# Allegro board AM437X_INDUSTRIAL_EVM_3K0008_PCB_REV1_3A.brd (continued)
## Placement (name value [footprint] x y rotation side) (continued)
R404  0  [SM-7351-RES-0402]  62.99 81.91 180 bottom
R405  0  [SM-7351-RES-0402]  60.45 81.91 0 bottom
R406  0  [SM-7351-RES-0402]  57.15 81.79 180 bottom
R407  0  [SM-7351-RES-0402]  136.08 80.77 180 bottom
R408  0  [SM-7351-RES-0402]  57.15 80.77 180 bottom
R409  10K, 1%  [SM-7351-RES-0402]  111.89 80.64 180 bottom
R410  0  [SM-7351-RES-0402]  60.45 80.64 0 bottom
R411  0  [SM-7351-RES-0402]  3.3 80.14 180 bottom
R412  10K  [SM-7351-RES-0402]  24.26 79.88 90 bottom
R413  0  [SM-7351-RES-0402]  136.08 79.5 180 bottom
R414  100  [SM-7351-RES-0402]  130.3 79.5 180 bottom
R415  49.9  [SM-7351-RES-0402]  111.89 79.38 0 bottom
R416  0  [SM-7351-RES-0402]  60.45 79.38 180 bottom
R417  0  [SM-7351-RES-0402]  25.91 79.38 0 bottom
R418  2.2K  [SM-7351-RES-0402]  102.36 78.74 0 bottom
R419  0  [SM-7351-RES-0402]  100.2 78.74 0 bottom
R420  0  [SM-7351-RES-0402]  4.83 78.23 0 bottom
R421  0  [SM-7351-RES-0402]  125.86 77.85 270 bottom
R422  0  [SM-7351-RES-0603]  85.85 77.72 90 bottom
R423  0  [SM-7351-RES-0603]  84.2 77.72 90 bottom
R424  2.2K  [SM-7351-RES-0402]  102.36 77.6 0 bottom
R425  0  [SM-7351-RES-0402]  100.2 77.6 0 bottom
R426  10K  [SM-7351-RES-0402]  130.3 77.22 180 bottom
R427  0  [SM-7351-RES-0603]  96.14 76.2 90 bottom
R428  0  [SM-7351-RES-0603]  94.36 76.2 90 bottom
R429  0  [SM-7351-RES-0402]  130.94 75.69 180 bottom
R430  0  [SM-7351-RES-0402]  100.2 75.56 180 bottom
R431  0  [SM-7351-RES-0402]  18.16 74.68 0 bottom
R432  0  [SM-7351-RES-0402]  100.2 74.55 180 bottom
R433  4.7K  [SM-7351-RES-0402]  130.94 74.42 180 bottom
R434  0  [SM-7351-RES-0402]  60.32 74.04 0 bottom
R435  0  [SM-7351-RES-0402]  107.57 73.91 0 bottom
R436  0  [SM-7351-RES-0402]  107.57 72.77 0 bottom
R437  0  [SM-7351-RES-0402]  64.14 72.26 0 bottom
R438  0  [SM-7351-RES-0402]  20.95 71.25 0 bottom
R439  22  [SM-7351-RES-0402]  64.14 71.12 0 bottom
R440  0  [SM-7351-RES-0402]  107.57 70.36 180 bottom
R441  0  [SM-7351-RES-0402]  33.4 70.36 0 bottom
R442  22  [SM-7351-RES-0402]  64.14 69.85 0 bottom
R443  0  [SM-7351-RES-0402]  33.4 69.22 0 bottom
R444  0  [SM-7351-RES-0402]  89.03 68.71 270 bottom
R445  0  [SM-7351-RES-0402]  33.4 68.07 0 bottom
R446  0  [SM-7351-RES-0603]  25.4 67.28 270 bottom
R447  0  [SM-7351-RES-0402]  33.4 66.93 0 bottom
R448  0  [SM-7351-RES-0603]  2.79 66.9 270 bottom
R449  0  [SM-7351-RES-0402]  64.14 66.67 0 bottom
R450  0  [SM-7351-RES-0402]  101.98 66.04 180 bottom
R451  0  [SM-7351-RES-0603]  119.31 65.66 270 bottom
R452  2.2K  [SM-7351-RES-0402]  33.4 65.63 180 bottom
R453  0  [SM-7351-RES-0402]  64.14 65.53 0 bottom
R454  0  [SM-7351-RES-0402]  101.98 64.9 180 bottom
R455  2.2K  [SM-7351-RES-0402]  33.4 64.48 0 bottom
R456  0  [SM-7351-RES-0603]  70.48 64.39 180 bottom
R457  0  [SM-7351-RES-0402]  64.14 64.39 0 bottom
R458  10K  [SM-7351-RES-0402]  59.94 63.88 270 bottom
R459  0  [SM-7351-RES-0402]  33.4 63.25 180 bottom
R460  12K, 1%  [SM-7351-RES-0402]  122.55 62.74 90 bottom
R461  0  [SM-7351-RES-0402]  33.4 62.23 0 bottom
R462  2.2K  [SM-7351-RES-0402]  27.43 62.23 0 bottom
R463  0  [SM-7351-RES-0603]  70.48 61.85 180 bottom
R464  4.87K  [SM-7351-RES-0402]  25.15 61.59 90 bottom
R465  0  [SM-7351-RES-0402]  65.41 61.09 0 bottom
R466  0  [SM-7351-RES-0402]  33.4 61.09 0 bottom
R467  0  [SM-7351-RES-0402]  90.9 60.29 0 bottom
R468  0  [SM-7351-RES-0402]  61.09 59.31 0 bottom
R469  0  [SM-7351-RES-0402]  64.14 59.18 0 bottom
R470  2.2K, 1/8W  [SM-7351-RES-0402]  80.9 58.93 0 bottom
R471  0  [SM-7351-RES-0402]  64.14 57.91 0 bottom
R472  10K  [SM-7351-RES-0402]  134.11 56.77 90 bottom
R473  0  [SM-7351-RES-0402]  64.14 56.64 0 bottom
R474  2.2K, 1/8W  [SM-7351-RES-0402]  81.66 56.39 270 bottom
R475  0  [SM-7351-RES-0402]  3.94 56.35 180 bottom
R476  4.99K  [SM-7351-RES-0402]  104.14 56.26 180 bottom
R477  0  [SM-7351-RES-0402]  134.11 54.1 270 bottom
R478  0  [SM-7351-RES-0402]  133.1 54.1 90 bottom
R479  10K  [SM-7351-RES-0402]  108.08 53.09 270 bottom
R480  49.9  [SM-7351-RES-0402]  45.97 51.82 180 bottom
R481  18K  [SM-7351-RES-0402]  45.97 50.55 0 bottom
R482  0  [SM-7351-RES-0402]  114.81 49.91 0 bottom
R483  0  [SM-7351-RES-0603]  5.71 47.62 270 bottom
R484  0  [SM-7351-RES-0402]  74.17 47.5 90 bottom
R485  0  [SM-7351-RES-0603]  9.02 47.37 270 bottom
R486  0  [SM-7351-RES-0603]  45.02 46.99 180 bottom
R487  0  [SM-7351-RES-0402]  133.86 46.86 270 bottom
R488  0  [SM-7351-RES-0603]  110.56 46.86 0 bottom
R489  0  [SM-7351-RES-0402]  127.64 45.59 90 bottom
R490  0  [SM-7351-RES-0402]  41.27 43.43 270 bottom
R491  15K,1%  [SM-7351-RES-0402]  109.6 43.31 180 bottom
R492  49.9  [SM-7351-RES-0402]  109.6 42.04 0 bottom
R493  0  [SM-7351-RES-0603]  20.95 41.78 90 bottom
R494  0  [SM-7351-RES-0402]  63.12 40.51 180 bottom
R495  4.99K  [SM-7351-RES-0402]  38.61 39.5 90 bottom
R496  4.99K  [SM-7351-RES-0402]  41.91 38.86 270 bottom
R497  22K  [SM-7351-RES-0402]  61.98 37.97 270 bottom
R498  100  [SM-7351-RES-0402]  131.44 37.72 180 bottom
R499  100  [SM-7351-RES-0402]  131.44 36.58 0 bottom
R500  33  [SM-7351-RES-0402]  55.63 36.2 180 bottom
R501  22K  [SM-7351-RES-0402]  61.98 35.94 90 bottom
R502  19.1K  [SM-7351-RES-0402]  59.94 35.94 270 bottom
R503  47  [SM-7351-RES-0402]  98.68 35.81 180 bottom
R504  240  [SM-7351-RES-0402]  79.63 35.56 0 bottom
R505  33  [SM-7351-RES-0402]  49.4 35.56 90 bottom
R506  19.1K  [SM-7351-RES-0402]  28.58 34.42 270 bottom
R507  49.9  [SM-7351-RES-0402]  100.33 34.16 180 bottom
R508  49.9  [SM-7351-RES-0402]  100.33 33.15 180 bottom
R509  22K  [SM-7351-RES-0402]  62.99 32.77 90 bottom
R510  19.1K  [SM-7351-RES-0402]  49.4 32.26 90 bottom
R511  49.9K  [SM-7351-RES-0402]  52.45 31.75 270 bottom
R512  120  [SM-7351-RES-0402]  7.62 31.12 0 bottom
R513  0  [SM-7351-RES-0603]  19.94 30.1 0 bottom
R514  0  [SM-7351-RES-0603]  15.24 30.1 0 bottom
R515  0  [SM-7351-RES-0402]  32.26 29.97 90 bottom
R516  47  [SM-7351-RES-0402]  100.46 29.08 180 bottom
R517  47  [SM-7351-RES-0402]  85.09 28.83 0 bottom
R518  22K  [SM-7351-RES-0402]  50.29 28.83 270 bottom
R519  10K  [SM-7351-RES-0402]  14.61 28.19 0 bottom
R520  47  [SM-7351-RES-0402]  100.46 27.94 180 bottom
R521  47  [SM-7351-RES-0402]  85.09 27.81 0 bottom
R522  47  [SM-7351-RES-0402]  85.09 26.8 0 bottom
R523  22K  [SM-7351-RES-0402]  63.5 26.54 90 bottom
R524  22K  [SM-7351-RES-0402]  62.48 26.54 90 bottom
R525  19.1K  [SM-7351-RES-0402]  60.45 26.54 270 bottom
R526  0  [SM-7351-RES-0603]  15.24 26.29 0 bottom
R527  47  [SM-7351-RES-0402]  95.76 25.27 90 bottom
R528  47  [SM-7351-RES-0402]  94.61 25.27 90 bottom
R529  47  [SM-7351-RES-0402]  93.47 25.27 90 bottom
R530  47  [SM-7351-RES-0402]  92.33 25.27 90 bottom
R531  47  [SM-7351-RES-0402]  91.19 25.27 90 bottom
R532  47  [SM-7351-RES-0402]  90.04 25.27 90 bottom
R533  47  [SM-7351-RES-0402]  88.9 25.27 90 bottom
R534  47  [SM-7351-RES-0402]  87.76 25.27 90 bottom
R535  47  [SM-7351-RES-0402]  86.61 25.27 90 bottom
R536  0.02  [SM-7351-RES-1206]  46.1 24.77 270 bottom
R537  0.02  [SM-7351-RES-1206]  43.18 24.77 270 bottom
R538  0.02  [SM-7351-RES-1206]  40.26 24.77 270 bottom
R539  22K  [SM-7351-RES-0402]  64.52 24.51 90 bottom
R540  0  [SM-7351-RES-0603]  15.24 24.38 0 bottom
R541  0  [SM-7351-RES-0402]  28.96 21.21 180 bottom
R542  10K  [SM-7351-RES-0402]  28.96 20.07 180 bottom
R543  0  [SM-7351-RES-1210]  42.67 19.56 90 bottom
R544  4.7K  [SM-7351-RES-0402]  37.72 17.65 270 bottom
R545  4.7K  [SM-7351-RES-0402]  36.7 17.65 270 bottom
R546  4.7K  [SM-7351-RES-0402]  35.69 17.65 270 bottom
R547  4.7K  [SM-7351-RES-0402]  34.67 17.65 270 bottom
R548  470K  [SM-7351-RES-0402]  53.09 16.89 180 bottom
R549  10K  [SM-7351-RES-0402]  97.28 15.62 180 bottom
R550  10K  [SM-7351-RES-0402]  58.29 13.84 0 bottom
R551  10K  [SM-7351-RES-0402]  58.26 12.83 0 bottom
R552  4.99K  [SM-7351-RES-0402]  17.65 12.32 270 bottom
R553  4.99K  [SM-7351-RES-0402]  37.59 12.1 270 bottom
R554  4.99K  [SM-7351-RES-0402]  25.6 11.91 270 bottom
R555  4.99K  [SM-7351-RES-0402]  29.77 11.82 270 bottom
R556  10K  [SM-7351-RES-0402]  58.26 11.68 0 bottom
R557  10K  [SM-7351-RES-0402]  58.26 10.54 0 bottom
R558  0  [SM-7351-RES-0402]  38.73 9.94 270 bottom
R559  95.3K  [SM-7351-RES-0402]  37.59 9.94 270 bottom
R560  4.99K  [SM-7351-RES-0402]  17.65 9.78 270 bottom
R561  0  [SM-7351-RES-0402]  25.6 9.75 270 bottom
R562  95.3K  [SM-7351-RES-0402]  24.46 9.75 270 bottom
R563  0  [SM-7351-RES-0402]  30.91 9.66 270 bottom
R564  95.3K  [SM-7351-RES-0402]  29.77 9.66 270 bottom
R565  4.99K  [SM-7351-RES-0402]  17.65 7.24 270 bottom
R566  0  [SM-7351-RES-0402]  70.23 83.31 270 top
SCKT1  AM437X ZDN Socket  [SCKBGA625]  80.48 66.9 90 top
SW1  B3SL  [SW_B3SL-1022P]  134.11 57.4 0 top
SW2  B3SL  [SW_B3SL-1022P]  134.05 35.69 0 top
TP1  TP  [TH_TP_5002]  57.53 117.35 0 top
TP2  TP  [TH_TP_5002]  55.12 101.09 0 top
TP3  TP1mm  [TP_SMD1MMCIRCLE]  25.27 96.36 0 top
TP4  TP1mm  [TP_SMD1MMCIRCLE]  135.76 92.33 0 top
TP5  TP1mm  [TP_SMD1MMCIRCLE]  135.76 90.3 0 top
TP6  TP1mm  [TP_SMD1MMCIRCLE]  125.6 83.95 0 top
TP7  TP  [TH_TP_5002]  95.5 83.57 0 top
TP8  TP1mm  [TP_SMD1MMCIRCLE]  25.27 72.01 0 top
TP9  TP  [TH_TP_5002]  137.41 71.88 0 top
TP10  TP1mm  [TP_SMD1MMCIRCLE]  110.24 70.74 0 top
TP11  TP  [TH_TP_5002]  2.67 52.7 0 top
TP12  TP  [TH_TP_5002]  31.88 46.61 0 top
TP13  TP  [TH_TP_5002]  103 40.51 0 top
TP14  TP  [TH_TP_5002]  123.19 34.29 0 top
TP15  TP  [TH_TP_5002]  21.34 26.29 0 top
TP16  TP  [TH_TP_5002]  63.88 2.92 0 top
TP17  TP1mm  [TP_SMD1MMCIRCLE]  116.84 107.7 90 bottom
TP18  TP1mm  [TP_SMD1MMCIRCLE]  35.94 85.09 180 bottom
TP19  TP1mm  [TP_SMD1MMCIRCLE]  75.56 79.38 180 bottom
TP20  TP1mm  [TP_SMD1MMCIRCLE]  80.77 77.72 180 bottom
TP21  TP1mm  [TP_SMD1MMCIRCLE]  65.66 77.22 180 bottom
U1  Red_Green_Yellow_LED  [LED-SM1210]  12.07 116.46 0 top
U2  Red_Green_Yellow_LED  [LED-SM1210]  20.07 116.46 0 top
U3  TPS5402D  [SOIC-8]  56.7 108.46 270 top
U4  SN65HVS882  [U_28_PWP]  75.56 101.66 0 top
U5  TPIC2810  [U_16_D]  87.76 101.46 180 top
U6  SN74LVC8T245  [TSSOP8X4-24-47M]  112.87 95.22 270 top
U7  TLK105L  [QFN5X5-32-39M]  27.56 91.28 270 top
U8  SN74LVC1G04  [SC70-5-43M]  120.65 83.82 180 top
U9  SN74LV244A  [TSSOP4X6-20]  60.07 82.3 90 top
U10  TPS5402D  [SOIC-8]  117.41 78.74 90 top
U11  -  [AM437X_ZDN]  80.48 67.15 90 top
U12  TLK105L  [QFN5X5-32-39M]  27.56 66.01 270 top
U13  FT2232HL  [LQFP64PIN]  117.23 60.96 180 top
U14  TPS5402D  [SOIC-8]  21.46 55.31 180 top
U15  TPS5402D  [SOIC-8]  40.45 52.45 270 top
U16  93LC56B  [SOIC_8]  114.17 47.5 90 top
U17  TPS5402D  [SOIC-8]  115.13 41.4 90 top
U18  OPA365  [SOT23-5]  28.58 35.56 90 top
U19  OPA365  [SOT23-5]  61.09 35.18 90 top
U20  MT41K256M16HA  [BGA9X14-96]  73.66 34.42 0 top
U21  MT41K256M16HA  [BGA9X14-96]  92.33 34.42 0 top
U22  OPA365  [SOT23-5]  50.29 32.38 270 top
U23  DRV8313  [HTSSOP-28P-47M]  42.42 31.75 0 top
U24  OPA365  [SOT23-5]  61.09 25.91 90 top
U25  TPS51200  [DRCPSO_10PIN]  93.85 14.22 180 top
U26  TPS386000  [QFN4X4-20-39M]  63.34 12.45 270 top
U27  TPD6E001  [U_10_RSE]  47.37 4.83 270 top
U28  LM4132  [SOT23-5]  127.25 114.55 270 bottom
U29  TPS22922B  [WCSP1X1-6-20M]  66.17 107.95 90 bottom
U30  TPS79301  [U_6_DBV]  109.86 104.58 90 bottom
U31  TXS0102  [DCT8]  134.05 102.68 90 bottom
U32  CAT24C256W  [SOIC_8]  85.22 101.46 180 bottom
U33  CDCE913  [TSSOP5X4-14-47M]  23.88 100.33 180 bottom
U34  SN74AVC1T45  [SMDSC70-6]  125.98 94.23 180 bottom
U35  TPS62362  [BGA2X2-16]  101.95 93.18 0 bottom
U36  SN74LVC1G07  [U_5_DCK]  74.3 92.96 90 bottom
U37  KSZ9031RN  [QFN7X7-48]  43.18 92.71 270 bottom
U38  SN74AVC4T245  [U_16_PW]  133.35 92.46 180 bottom
U39  SN74LV244A  [TSSOP4X6-20]  60.07 89.79 90 bottom
U40  TPS22922B  [WCSP1X1-6-20M]  115.7 84.2 0 bottom
U41  SN74AVC2T244  [SON2X1-8-16M]  130.81 83.95 180 bottom
U42  SN74LVC1G07  [U_5_DCK]  30.35 81.03 180 bottom
U43  SN74LVC1G08  [SM-SO-SC70-5]  22.23 80.36 180 bottom
U44  SN74LVC1G08  [SM-SO-SC70-5]  15.49 75.69 180 bottom
U45  SN74AVC4T245  [U_16_PW]  126.75 69.6 180 bottom
U46  MX66L51235FMI  [SOIC_16PIN_DW]  42.55 65.28 90 bottom
U47  TPD2E001  [U_5_DRL]  131.95 62.86 180 bottom
U48  SN74LVC1G07  [U_5_DCK]  107.44 56.26 180 bottom
U49  SN74AVC2T244  [SON2X1-8-16M]  132.21 50.16 180 bottom
U50  SN74LVC1G00DCK  [U_5_DCK]  123.82 48.9 180 bottom
U51  SN74LVC1G07  [SC70-5-43M]  127 48.77 270 bottom
U52  TPS22922B  [WCSP1X1-6-20M]  42.16 46.99 180 bottom
U53  TPS22922B  [WCSP1X1-6-20M]  113.41 46.86 0 bottom
U54  SN74LVC1G07  [SC70-5-43M]  134.49 43.56 270 bottom
U55  SN65HVD78D  [SOIC_8]  24.64 43.43 180 bottom
U56  REF3025  [SOT23-3-44M]  53.85 38.99 180 bottom
U57  SN65HVD78D  [SOIC_8]  7.49 27.56 270 bottom
U58  SN74LVC8T245  [TSSOP8X4-24-47M]  34.42 24.64 270 bottom
U59  TPD2E001  [U_5_DRL]  53.21 18.67 90 bottom
Y1  24MHz  [XTAL2X3-30M]  72.99 88.87 90 top
Y2  25MHz  [SM_OSC_ABM3]  21.08 107.7 0 bottom
Y3  32.768KHz MC-306  [MC-306]  98.26 61.05 0 bottom
Y4  12MHz  [SM_OSC_ABM3]  126.43 56.01 90 bottom

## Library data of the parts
C1 C51 C67 C88 C96 C97 C99 C121 C122 C253 C326 C327 C337 = 1C_0.1uFCapacitor50V10%0402: Tolerance: TOLERANCE; User Part Number: USERPART#
C2 C21 C22 C28 C31 C43 C104 C105 C113 C117 C123 C134 C136 C161 C167 C168 C172 C182 C189 C214 C229 C244 C257 C266 C276 C280 C335 C341 C342 = 1C_10uFCapacitor16V10%0805
C3-C10 = 1C_0.022uFCapacitor16Vsmd0402: Tolerance: TOLERANCE; User Part Number: USERPART#
C11 C46 C72 C75 C82 = 1C_2200pFCapacitor50V10%SMD0402: Tolerance: TOLERANCE; User Part Number: USERPART#
C12 C45 C70 C74 C81 C95 C339 = 1C_10uFCapacitor35V10%0805
C13-C18 C20 C24 C25 C29 C30 C32-C34 C37 C39-C41 C44 C47 C48 C52 C53 C58-C64 C66 C69 C73 C76 C77 C79 C89 C90 C92 C94 C101 C114 C119 C126 C127 C139-C141 C145 C146 C152 C156 C158-C160 C166 C169 C170 C173 C178-C181 C183-C185 C187 C190 C192 C193 C195-C207 C209-C211 C213 C216 C217 C219-C221 C223-C227 C230 C231 C233-C236 C238-C242 C246 C247 C249 C250 C252 C256 C259 C260 C263-C265 C267 C270 C274 C275 C277-C279 C281-C285 C288-C292 C294-C297 C299 C301 C302 C304 C314-C316 C318-C320 C323 C324 C328 C329 C336 C343-C346 = 1C_0.01uFCapacitor16V10%0402: Tolerance: TOLERANCE; User Part Number: USERPART#
C19 C71 C151 C186 C191 C212 C218 C287 = 1C_1uFCapacitor10V10%0402: Tolerance: TOLERANCE; User Part Number: USERPART#
C23 C303 = 1C_10uFCapacitor50V10%1206
C26 C38 C55 C57 C65 C78 C103 C106 C107 C112 C116 C125 C142 C143 C147-C150 C153 C155 C157 C162-C164 C174 C194 C208 C215 C222 C232 C237 C306 C307 C311-C313 C317 C330 C338 = 1C_0.1uFCapacitor16V10%0402: Tolerance: TOLERANCE; User Part Number: USERPART#
C27 C131 C271 = 1C_220uFCapacitor16V10%Tantalum
C35 C36 = 1C_24pFCapacitor50V5%SMD0402: Tolerance: TOLERANCE; User Part Number: USERPART#
C49 C50 = 1C_47uFCapacitor16V20%1206
C54 C56 C109-C111 C154 C300 C308 C321 C332 C347 C351 C352 = 1C_0.001uFCapacitor50V5%0402: Tolerance: TOLERANCE; User Part Number: USERPART#
C68 C348-C350 = 1C_47nFCapacitor25V10%smd0402: Tolerance: TOLERANCE; User Part Number: USERPART#
C80 C102 C124 C175 C254 C269 C272 = 1C_22uFCapacitor16V10%0805
C83 C84 C286 C309 C325 C333 C334 = 1C_180pF50V5%SMD0402: Tolerance: TOLERANCE; User Part Number: USERPART#
C85 C86 C91 C93 C176 C177 C298 C305 C310 C331 = 1C_100pFCapacitor16V10%0402: Tolerance: TOLERANCE; User Part Number: USERPART#
C87 C100 C293 = 1C_0.47uFCapacitor16V10%0402: Tolerance: TOLERANCE; User Part Number: USERPART#
C98 = 1C_1uFCapacitor50V10%0603: Tolerance: TOLERANCE; User Part Number: USERPART#
C108 = 1C_10pFCapacitor50V1%smd0402: Tolerance: TOLERANCE; User Part Number: USERPART#
C115 C120 C245 C251 C258 = 1C_4.7uFCapacitor16V10%0603
C118 C171 C262 C268 C273 = 1C_1uFCapacitor50V10%0603
C128 C138 C228 = 1C_2.2uF16V10%SMD0805
C129 C130 C255 C261 = 1C_18pFCapacitor16V10%0402: Tolerance: TOLERANCE; User Part Number: USERPART#
C132 C133 = 1C_2.2uFCapacitor6.3V10%smd0603
C135 C243 C248 = 1C_15pFCapacitor50V10%smd0402: Tolerance: TOLERANCE; User Part Number: USERPART#
C137 C188 = 1C_4700pFCapacitor50V10%0402: Tolerance: TOLERANCE; User Part Number: USERPART#
C144 C165 = 1C_10uFCapacitor6.3V20%0603
C322 C340 = 1C_100uFCapacitor35V20%ElecPoly
D1 D11 D13 D14 D16 = 1E_Diode_500mA30V
D2-D10 D12 = 1F_LED_Green
D15 = 1F_LED_Red
D17 D19 D22 = 1E_Diode_MBRS140T3
D18 D21 = 1E_Diode_SMCJ26CA
D20 = Diode200mA250V
F1 = 1P_Fuse_4A
FB1 FB6-FB12 FB14 FB17 = 1L_FerBead_180ohm200mA
FB2-FB5 = 1L_FerriteBead_600mA10ohm
FB13 FB15 FB16 = 1L_FerriteBead_220ohm2A
J1 = Header20x2_0.1in_Female
J2 = 2H_Header_3x1
J3 = 2H_Header5x2
J4 = 2J_ConnectorRJ45_Gigabit
J5 = 2C_Conn_FPC_AXK_24pin
J6 J9 = 2J_ConnectorRJ45_10_100MbAMDIX
J7 = 2H_Header10x2_CJTAG
J8 J11 = 2H_Header_2x1
J10 = 2C_Conn_M12_8pin_female
J12 = 2J_Conn_PwrJack_RAPC722
J13 J14 = 2C_Conn_LeadScrewDown_2pin
J15 = 2H_Header_6x1
J16 = 2H_Header30x2_female_2mm
J17 = 2C_Conn_LeadScrewDown_3pin
J18 = 2C_MicroUSBAB
J19 = 2C_Conn_microSD_8: User Part Number: X; Tolerance: X
L1-L3 = 1L_4.7uHInductor30%3.1Asmd
L4 = 1L_47uHInductor20%1.6Asmd
L5 = 1L_1uHInductor20%4.5Asmd
L6 = 1L_100uHInductor20%450mAsmd
L7 = 1L_100uHInductor20%1.02Asmd
L8 = 1L_82uHInductor20%370mAsmd
L9 = 1L_47uHInductor20%720mAsmd
Q1-Q8 = 1Q_MOSFET_NChan_BSS138
Q9 = 1Q_MOSFET_PChan_FDT434P
Q10 = 1Q_MOSFET_PChan_BSS84
R1 R7 R9 R11 R23-R30 R35-R42 R47-R49 R233 R274 R276 R278 R361 = 1R_100KOhmResistor1/16W0402
R2 R3 R54 R69 R75 R81 R135 R169 R172 R178 R224 R226 R228 R231 R234 R236 R237 R244 R266 R267 R297 R300 R305 R314-R321 R328-R336 R340-R343 R345 R347 R392 R393 R395 R396 R399 R400 R412 R426 R458 R472 R479 R519 R542 R549-R551 R556 R557 = 1R_10KOhmResistor1/16W0402
R4-R6 R268 R271 R272 R280-R287 = 1R_150ohm1/16W1%SMD0402
R8 R10 R12 R21 R22 R52 R60-R63 R65 R70-R74 R80 R83-R92 R97-R99 R103-R105 R109-R120 R124 R126 R129 R132-R134 R138 R140 R143 R148 R152 R157 R163 R170 R186 R187 R202 R232 R238-R243 R245-R265 R275 R277 R279 R296 R304 R308-R310 R324 R325 R348 R350-R352 R354-R357 R359 R360 R363 R364 R374-R376 R380-R385 R388 R404 R406-R408 R411 R413 R416 R417 R419-R421 R425 R429-R432 R434-R438 R440 R444 R450 R454 R459 R465 R467 R468 R471 R473 R475 R477 R478 R482 R487 R489 R490 R494 R515 R541 R558 R561 R563 R566 = 1R_ZeroOhmResistor1/16W0402
R13 R17 R139 R142 R149 R190 R215 R273 R299 R303 R313 R346 R358 R379 R401 R422 R423 R427 R428 R446 R448 R451 R456 R463 R483 R485 R486 R488 R493 R513 R514 R526 R540 = 1R_ZeroOhmResistor1/16W0603
R14 = 1R_34KOhmResistor1/10W1%0402
R15 R16 R160 R168 R353 R402 R403 R433 R544-R547 = 1R_4.7KOhmResistor1/16W0402
R18 R94 R156 R175 R182 = 1R_51Kohm1/16W1%smd0402
R19 = 1R_4.75KohmResistor1/16W1%0402
R20 R201 R204 R223 R311 R312 R323 R386 R387 R500 R505 = 1R_33ohmResistor1/16W5%0402
R31 R43 R50 R56 R101 R106 R125 R131 R162 R164 R302 R415 R480 R492 R507 R508 = 1R_49.9OhmResistor1/16W0402
R32 = 1R_12.1KohmResistor1/16W1%0402
R33 R34 = ZeroOhmResistor1/16W0402
R44 R46 R51 R55 R57 R77 R96 R100 R108 R122 R145 R180 R418 R424 R452 R462 = 1R_2.2KOhmResistor1/16W0402
R45 R53 R193 R195 R197 R200 R203 R209 R211 R222 R366 R369 R372 R394 R397 R398 = 1R_1KOhmResistor1/16W0402
R58 R64 R68 = 1R_4.02KohmResistor1/16W1%0402
R59 R67 R76 R78 R79 R128 R136 R137 R141 R144 R146 R147 R150 R151 R153 R155 R158 R161 R167 R174 R177 R179 R337 R339 R344 R349 R377 R378 R390 R391 R405 R410 R441 R443 R445 R447 R449 R453 R457 R461 R466 R469 R484 = 1R_ZeroOhmResistor1/16W0402: signal model: 1R_ZEROOHMRESISTOR1/16W0402_SM-_0
R66 = 1R_1.5KohmResistor1/16W5%0402
R82 R307 = 1MOhmResistor1/16W0402
R93 = 1R_8.06Kohm1/16W1%smd0402
R95 R235 = 1R_60.4Kohm1/16W1%smd0402
R102 R107 R121 R123 R365 R367 R368 R370 R371 R373 R439 R442 = 1R_22OhmResistor1/16W1%0402: signal model: 1R_22OHMRESISTOR1/16W1%0402_SM-_22
R127 R130 R455 = 1R_2.2KOhmResistor1/16W0402: signal model: 1R_2.2KOHMRESISTOR1/16W0402_SM-_2.2K
R154 R559 R562 R564 = 95.3KOhmResistor1/16W0402
R159 R173 R191 R192 R212 R511 = 1R_49.9KOhmResistor1/16W0402
R165 = 1R_16KOhmResistor1/16W1%0402
R166 = 1R_3.01KohmResistor1/16W1%0402
R171 R183 R269 R270 = 1R_220ohm1/10W1%smd0402
R176 = 1R_20.5Kohm1/16W1%smd0402
R181 = 1R_40.2Kohm1/16W1%smd0402
R184 R185 R188 R189 R207 R497 R501 R509 R518 R523 R524 R539 = 1R_22Kohm1/16W1%SMD0402
R194 R196 R208 R210 = 1R_28.7Kohm1/16W1%smd0402
R198 R504 = 1R_240OhmResistor1/16W0402
R199 R205 R206 R216-R221 R503 R516 R517 R520-R522 R527-R535 = 1R_47ohm1/16W1%smd0402
R213 R476 R495 R496 R552-R555 R560 R565 = 1R_4.99KOhmResistor1/16W0402
R214 = 1R_402Kohm1/16W1%smd0402
R225 = 1R_10ohm1/16W5%smd0402
R227 R230 = 1R_14KOhmResistor1/16W0402
R229 = 1R_24Kohm1/16W1%smd0402
R288-R295 = 1R_1.2Kohm1/3W1%SMDMELF0102
R298 R491 = 1R_15Kohm1/16W1%smd0402
R301 = 1R_30.1Kohm1/16W1%smd0402
R306 = 1R_39Kohm1/16W5%smd0402
R322 = 1R_25Kohm1/10W0.1%smd0603
R326 R327 = 1R_ZeroOhmResistor1/16W0603: signal model: 1R_ZEROOHMRESISTOR1/16W0603_SM-_0
R338 = 49.9ohm1/3W1%SMDMELF0102
R362 R464 = 1R_4.87Kohm1/16W1%smd0402
R389 R414 R498 R499 = 1R_100ohm1/16W1%SMD0402
R409 = 1R_10KOhmResistor1/10W1%0402
R460 = 1R_12Kohm1/16W1%SMD0402
R470 R474 = 1R_2.2KohmResistor1/8W1%0402
R481 = 1R_18KohmResistor1/10W1%smd0402
R502 R506 R510 R525 = 1R_19.1Kohm1/16W1%smd0402
R512 = 1R_120ohm1/16W1%smd0402
R536-R538 = 1R_0.02ohm1W1%smd1206
R543 = 1R_ZeroOhmResistor1/2W1210
R548 = 470Kohm1/16W1%SMD0402
SCKT1 = AM437X_ZDN_Processor_Socket
SW1 SW2 = 2W_Switch_Pushbuttonsmd
TP1 TP2 TP7 TP9 TP11-TP16 = 2H_TestPointThroughHole
TP3-TP6 TP8 TP10 TP17-TP21 = 2H_Testpoint_SMD1mmCircle
U1 U2 = 1F_LED_Tricolor_RedGreenYellow
U3 U10 U14 U15 U17 = 1A_TPS5402
U4 = SN65HVS882
U5 = TPIC2810
U6 U58 = 1A_SN74LVC8T245
U7 U12 = 1A_TLK105L
U8 = 1A_SN74LVC1G04
U9 U39 = 1A_SN74LV244APWRG3
U11 = am437x_ZDN_Industrial EVM
U13 = 1A_FT2232_2
U16 = 1A_93C56EEPROM2Kbit
U18 U19 U22 U24 = 1A_OPA365
U20 U21 = 1A_MT41K256M16HA
U23 = 1A_DRV8313
U25 = TPS51200
U26 = 1A_TPS386000
U27 = 1A_TPD6E001RSE
U28 = 1A_LM4132
U29 U40 U52 U53 = 1A_TPS22922B
U30 = 1A_TPS79301
U31 = 1A_TXS0102
U32 = 1A_CAT24C256W
U33 = 1A_CDCE913
U34 = 1A_SN74AVC1T45
U35 = 1A_TPS62362
U36 U42 U48 U51 U54 = 1A_SN74LVC1G07
U37 = 1A_KSZ9031RNX
U38 U45 = 1A_SN74AVC4T245
U41 U49 = 1A_SN74AVC2T244
U43 U44 = SN74LVC1G08DCKT_SC70
U46 = 1A_MX66L51235FMI
U47 U59 = 1A_TPD2E001DRL
U50 = 1A_SN74LVC1G00DCK
U55 U57 = 1A_SN65HVD78
U56 = 1A_REF3025
Y1 = 1Y_Crystal24MHzSCM
Y2 = 1Y_Crystal25MHzABM3
Y3 = 1Y_Crystal_SMD32_768kHz
Y4 = 1Y_Crystal12MHzABM3

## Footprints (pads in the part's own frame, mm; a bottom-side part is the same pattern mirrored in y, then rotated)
AM437X_ZDN
  round 0.28 smd: A1(-7.8,7.8) A2(-7.15,7.8) A3(-6.5,7.8) A4(-5.85,7.8) A5(-5.2,7.8) A6(-4.55,7.8) A7(-3.9,7.8) A8(-3.25,7.8) A9(-2.6,7.8) A10(-1.95,7.8) A11(-1.3,7.8) A12(-0.65,7.8) A13(0,7.8) A14(0.65,7.8) A15(1.3,7.8) A16(1.95,7.8) A17(2.6,7.8) A18(3.25,7.8) A19(3.9,7.8) A20(4.55,7.8) A21(5.2,7.8) A22(5.85,7.8) A23(6.5,7.8) A24(7.15,7.8) A25(7.8,7.8) AA1(-7.8,-5.2) AA2(-7.15,-5.2) AA3(-6.5,-5.2) AA7(-3.9,-5.2) AA9(-2.6,-5.2) AA10(-1.95,-5.2) AA12(-0.65,-5.2) AA13(0,-5.2) AA15(1.3,-5.2) AA16(1.95,-5.2) AA18(3.25,-5.2) AA19(3.9,-5.2) AA23(6.5,-5.2) AA24(7.15,-5.2) AA25(7.8,-5.2) AB1(-7.8,-5.85) AB2(-7.15,-5.85) AB6(-4.55,-5.85) AB7(-3.9,-5.85) AB9(-2.6,-5.85) AB10(-1.95,-5.85) AB12(-0.65,-5.85) AB13(0,-5.85) AB15(1.3,-5.85) AB16(1.95,-5.85) AB18(3.25,-5.85) AB19(3.9,-5.85) AB20(4.55,-5.85) AB24(7.15,-5.85) AB25(7.8,-5.85) AC1(-7.8,-6.5) AC2(-7.15,-6.5) AC3(-6.5,-6.5) AC5(-5.2,-6.5) AC6(-4.55,-6.5) AC7(-3.9,-6.5) AC9(-2.6,-6.5) AC10(-1.95,-6.5) AC12(-0.65,-6.5) AC13(0,-6.5) AC15(1.3,-6.5) AC16(1.95,-6.5) AC18(3.25,-6.5) AC20(4.55,-6.5) AC21(5.2,-6.5) AC23(6.5,-6.5) AC24(7.15,-6.5) AC25(7.8,-6.5) AD1(-7.8,-7.15) AD2(-7.15,-7.15) AD3(-6.5,-7.15) AD4(-5.85,-7.15) AD5(-5.2,-7.15) AD6(-4.55,-7.15) AD7(-3.9,-7.15) AD8(-3.25,-7.15) AD9(-2.6,-7.15) AD10(-1.95,-7.15) AD11(-1.3,-7.15) AD12(-0.65,-7.15) AD13(0,-7.15) AD14(0.65,-7.15) AD15(1.3,-7.15) AD16(1.95,-7.15) AD17(2.6,-7.15) AD18(3.25,-7.15) AD19(3.9,-7.15) AD20(4.55,-7.15) AD21(5.2,-7.15) AD22(5.85,-7.15) AD23(6.5,-7.15) AD24(7.15,-7.15) AD25(7.8,-7.15) AE1(-7.8,-7.8) AE2(-7.15,-7.8) AE3(-6.5,-7.8) AE4(-5.85,-7.8) AE5(-5.2,-7.8) AE6(-4.55,-7.8) AE7(-3.9,-7.8) AE8(-3.25,-7.8) AE9(-2.6,-7.8) AE10(-1.95,-7.8) AE11(-1.3,-7.8) AE12(-0.65,-7.8) AE13(0,-7.8) AE14(0.65,-7.8) AE15(1.3,-7.8) AE16(1.95,-7.8) AE17(2.6,-7.8) AE18(3.25,-7.8) AE19(3.9,-7.8) AE20(4.55,-7.8) AE21(5.2,-7.8) AE22(5.85,-7.8) AE23(6.5,-7.8) AE24(7.15,-7.8) AE25(7.8,-7.8) B1(-7.8,7.15) B2(-7.15,7.15) B3(-6.5,7.15) B4(-5.85,7.15) B5(-5.2,7.15) B6(-4.55,7.15) B7(-3.9,7.15) B8(-3.25,7.15) B9(-2.6,7.15) B10(-1.95,7.15) B11(-1.3,7.15) B12(-0.65,7.15) B13(0,7.15) B14(0.65,7.15) B15(1.3,7.15) B16(1.95,7.15) B17(2.6,7.15) B18(3.25,7.15) B19(3.9,7.15) B20(4.55,7.15) B21(5.2,7.15) B22(5.85,7.15) B23(6.5,7.15) B24(7.15,7.15) B25(7.8,7.15) C1(-7.8,6.5) C2(-7.15,6.5) C3(-6.5,6.5) C5(-5.2,6.5) C6(-4.55,6.5) C8(-3.25,6.5) C10(-1.95,6.5) C11(-1.3,6.5) C13(0,6.5) C14(0.65,6.5) C16(1.95,6.5) C17(2.6,6.5) C19(3.9,6.5) C20(4.55,6.5) C21(5.2,6.5) C23(6.5,6.5) C24(7.15,6.5) C25(7.8,6.5) D1(-7.8,5.85) D2(-7.15,5.85) D6(-4.55,5.85) D7(-3.9,5.85) D8(-3.25,5.85) D10(-1.95,5.85) D11(-1.3,5.85) D13(0,5.85) D14(0.65,5.85) D16(1.95,5.85) D17(2.6,5.85) D19(3.9,5.85) D20(4.55,5.85) D24(7.15,5.85) D25(7.8,5.85) E1(-7.8,5.2) E2(-7.15,5.2) E3(-6.5,5.2) E7(-3.9,5.2) E8(-3.25,5.2) E10(-1.95,5.2) E11(-1.3,5.2) E13(0,5.2) E14(0.65,5.2) E16(1.95,5.2) E17(2.6,5.2) E19(3.9,5.2) E23(6.5,5.2) E24(7.15,5.2) E25(7.8,5.2) F1(-7.8,4.55) F2(-7.15,4.55) F3(-6.5,4.55) F4(-5.85,4.55) F6(-4.55,4.55) F7(-3.9,4.55) F8(-3.25,4.55) F10(-1.95,4.55) F11(-1.3,4.55) F13(0,4.55) F14(0.65,4.55) F16(1.95,4.55) F17(2.6,4.55) F19(3.9,4.55) F20(4.55,4.55) F22(5.85,4.55) F23(6.5,4.55) F24(7.15,4.55) F25(7.8,4.55) G1(-7.8,3.9) G2(-7.15,3.9) G3(-6.5,3.9) G4(-5.85,3.9) G5(-5.2,3.9) G6(-4.55,3.9) G8(-3.25,3.9) G10(-1.95,3.9) G11(-1.3,3.9) G13(0,3.9) G14(0.65,3.9) G16(1.95,3.9) G17(2.6,3.9) G20(4.55,3.9) G21(5.2,3.9) G22(5.85,3.9) G24(7.15,3.9) G25(7.8,3.9) H1(-7.8,3.25) H2(-7.15,3.25) H8(-3.25,3.25) H9(-2.6,3.25) H10(-1.95,3.25) H11(-1.3,3.25) H12(-0.65,3.25) H13(0,3.25) H14(0.65,3.25) H15(1.3,3.25) H16(1.95,3.25) H17(2.6,3.25) H18(3.25,3.25) H19(3.9,3.25) H20(4.55,3.25) H21(5.2,3.25) H22(5.85,3.25) H23(6.5,3.25) H24(7.15,3.25) H25(7.8,3.25) J1(-7.8,2.6) J2(-7.15,2.6) J3(-6.5,2.6) J4(-5.85,2.6) J5(-5.2,2.6) J6(-4.55,2.6) J7(-3.9,2.6) J8(-3.25,2.6) J9(-2.6,2.6) J10(-1.95,2.6) J11(-1.3,2.6) J12(-0.65,2.6) J13(0,2.6) J14(0.65,2.6) J15(1.3,2.6) J16(1.95,2.6) J17(2.6,2.6) J18(3.25,2.6) J24(7.15,2.6) J25(7.8,2.6) K1(-7.8,1.95) K2(-7.15,1.95) K3(-6.5,1.95) K4(-5.85,1.95) K5(-5.2,1.95) K6(-4.55,1.95) K7(-3.9,1.95) K8(-3.25,1.95) K9(-2.6,1.95) K11(-1.3,1.95) K12(-0.65,1.95) K14(0.65,1.95) K15(1.3,1.95) K17(2.6,1.95) K18(3.25,1.95) K19(3.9,1.95) K20(4.55,1.95) K21(5.2,1.95) K22(5.85,1.95) K23(6.5,1.95) K24(7.15,1.95) K25(7.8,1.95) L1(-7.8,1.3) L2(-7.15,1.3) L8(-3.25,1.3) L9(-2.6,1.3) L11(-1.3,1.3) L12(-0.65,1.3) L14(0.65,1.3) L15(1.3,1.3) L17(2.6,1.3) L18(3.25,1.3) L19(3.9,1.3) L20(4.55,1.3) L21(5.2,1.3) L22(5.85,1.3) L23(6.5,1.3) L24(7.15,1.3) L25(7.8,1.3) M1(-7.8,0.65) M2(-7.15,0.65) M3(-6.5,0.65) M4(-5.85,0.65) M5(-5.2,0.65) M6(-4.55,0.65) M7(-3.9,0.65) M8(-3.25,0.65) M9(-2.6,0.65) M10(-1.95,0.65) M11(-1.3,0.65) M12(-0.65,0.65) M13(0,0.65) M14(0.65,0.65) M15(1.3,0.65) M16(1.95,0.65) M17(2.6,0.65) M18(3.25,0.65) M24(7.15,0.65) M25(7.8,0.65) N1(-7.8,0) N2(-7.15,0) N3(-6.5,0) N4(-5.85,0) N5(-5.2,0) N6(-4.55,0) N7(-3.9,0) N8(-3.25,0) N9(-2.6,0) N10(-1.95,0) N11(-1.3,0) N12(-0.65,0) N13(0,0) N14(0.65,0) N15(1.3,0) N16(1.95,0) N17(2.6,0) N18(3.25,0) N19(3.9,0) N20(4.55,0) N21(5.2,0) N22(5.85,0) N23(6.5,0) N24(7.15,0) N25(7.8,0) P1(-7.8,-0.65) P2(-7.15,-0.65) P8(-3.25,-0.65) P9(-2.6,-0.65) P10(-1.95,-0.65) P11(-1.3,-0.65) P12(-0.65,-0.65) P13(0,-0.65) P14(0.65,-0.65) P15(1.3,-0.65) P16(1.95,-0.65) P17(2.6,-0.65) P18(3.25,-0.65) P19(3.9,-0.65) P20(4.55,-0.65) P21(5.2,-0.65) P22(5.85,-0.65) P23(6.5,-0.65) P24(7.15,-0.65) P25(7.8,-0.65) R1(-7.8,-1.3) R2(-7.15,-1.3) R3(-6.5,-1.3) R4(-5.85,-1.3) R5(-5.2,-1.3) R6(-4.55,-1.3) R7(-3.9,-1.3) R8(-3.25,-1.3) R9(-2.6,-1.3) R11(-1.3,-1.3) R12(-0.65,-1.3) R14(0.65,-1.3) R15(1.3,-1.3) R17(2.6,-1.3) R18(3.25,-1.3) R24(7.15,-1.3) R25(7.8,-1.3) T1(-7.8,-1.95) T2(-7.15,-1.95) T3(-6.5,-1.95) T4(-5.85,-1.95) T5(-5.2,-1.95) T6(-4.55,-1.95) T7(-3.9,-1.95) T8(-3.25,-1.95) T9(-2.6,-1.95) T11(-1.3,-1.95) T12(-0.65,-1.95) T14(0.65,-1.95) T15(1.3,-1.95) T17(2.6,-1.95) T18(3.25,-1.95) T19(3.9,-1.95) T20(4.55,-1.95) T21(5.2,-1.95) T22(5.85,-1.95) T23(6.5,-1.95) T24(7.15,-1.95) T25(7.8,-1.95) U1(-7.8,-2.6) U2(-7.15,-2.6) U8(-3.25,-2.6) U9(-2.6,-2.6) U10(-1.95,-2.6) U11(-1.3,-2.6) U12(-0.65,-2.6) U13(0,-2.6) U14(0.65,-2.6) U15(1.3,-2.6) U16(1.95,-2.6) U17(2.6,-2.6) U18(3.25,-2.6) U19(3.9,-2.6) U20(4.55,-2.6) U21(5.2,-2.6) U22(5.85,-2.6) U23(6.5,-2.6) U24(7.15,-2.6) U25(7.8,-2.6) V1(-7.8,-3.25) V2(-7.15,-3.25) V3(-6.5,-3.25) V4(-5.85,-3.25) V5(-5.2,-3.25) V6(-4.55,-3.25) V7(-3.9,-3.25) V8(-3.25,-3.25) V9(-2.6,-3.25) V10(-1.95,-3.25) V11(-1.3,-3.25) V12(-0.65,-3.25) V13(0,-3.25) V14(0.65,-3.25) V15(1.3,-3.25) V16(1.95,-3.25) V17(2.6,-3.25) V18(3.25,-3.25) V24(7.15,-3.25) V25(7.8,-3.25) W1(-7.8,-3.9) W2(-7.15,-3.9) W4(-5.85,-3.9) W5(-5.2,-3.9) W6(-4.55,-3.9) W10(-1.95,-3.9) W12(-0.65,-3.9) W13(0,-3.9) W15(1.3,-3.9) W16(1.95,-3.9) W18(3.25,-3.9) W20(4.55,-3.9) W21(5.2,-3.9) W22(5.85,-3.9) W23(6.5,-3.9) W24(7.15,-3.9) W25(7.8,-3.9) Y1(-7.8,-4.55) Y2(-7.15,-4.55) Y3(-6.5,-4.55) Y4(-5.85,-4.55) Y6(-4.55,-4.55) Y7(-3.9,-4.55) Y10(-1.95,-4.55) Y12(-0.65,-4.55) Y13(0,-4.55) Y15(1.3,-4.55) Y16(1.95,-4.55) Y18(3.25,-4.55) Y19(3.9,-4.55) Y20(4.55,-4.55) Y22(5.85,-4.55) Y23(6.5,-4.55) Y24(7.15,-4.55) Y25(7.8,-4.55)
BGA2X2-16
  round 0.25 smd: A1(0.75,-0.75) A2(0.25,-0.75) A3(-0.25,-0.75) A4(-0.75,-0.75) B1(0.75,-0.25) B2(0.25,-0.25) B3(-0.25,-0.25) B4(-0.75,-0.25) C1(0.75,0.25) C2(0.25,0.25) C3(-0.25,0.25) C4(-0.75,0.25) D1(0.75,0.75) D2(0.25,0.75) D3(-0.25,0.75) D4(-0.75,0.75)
BGA9X14-96
  round 0.35 smd: A1(-3.2,6) A2(-2.4,6) A3(-1.6,6) A7(1.6,6) A8(2.4,6) A9(3.2,6) B1(-3.2,5.2) B2(-2.4,5.2) B3(-1.6,5.2) B7(1.6,5.2) B8(2.4,5.2) B9(3.2,5.2) C1(-3.2,4.4) C2(-2.4,4.4) C3(-1.6,4.4) C7(1.6,4.4) C8(2.4,4.4) C9(3.2,4.4) D1(-3.2,3.6) D2(-2.4,3.6) D3(-1.6,3.6) D7(1.6,3.6) D8(2.4,3.6) D9(3.2,3.6) E1(-3.2,2.8) E2(-2.4,2.8) E3(-1.6,2.8) E7(1.6,2.8) E8(2.4,2.8) E9(3.2,2.8) F1(-3.2,2) F2(-2.4,2) F3(-1.6,2) F7(1.6,2) F8(2.4,2) F9(3.2,2) G1(-3.2,1.2) G2(-2.4,1.2) G3(-1.6,1.2) G7(1.6,1.2) G8(2.4,1.2) G9(3.2,1.2) H1(-3.2,0.4) H2(-2.4,0.4) H3(-1.6,0.4) H7(1.6,0.4) H8(2.4,0.4) H9(3.2,0.4) J1(-3.2,-0.4) J2(-2.4,-0.4) J3(-1.6,-0.4) J7(1.6,-0.4) J8(2.4,-0.4) J9(3.2,-0.4) K1(-3.2,-1.2) K2(-2.4,-1.2) K3(-1.6,-1.2) K7(1.6,-1.2) K8(2.4,-1.2) K9(3.2,-1.2) L1(-3.2,-2) L2(-2.4,-2) L3(-1.6,-2) L7(1.6,-2) L8(2.4,-2) L9(3.2,-2) M1(-3.2,-2.8) M2(-2.4,-2.8) M3(-1.6,-2.8) M7(1.6,-2.8) M8(2.4,-2.8) M9(3.2,-2.8) N1(-3.2,-3.6) N2(-2.4,-3.6) N3(-1.6,-3.6) N7(1.6,-3.6) N8(2.4,-3.6) N9(3.2,-3.6) P1(-3.2,-4.4) P2(-2.4,-4.4) P3(-1.6,-4.4) P7(1.6,-4.4) P8(2.4,-4.4) P9(3.2,-4.4) R1(-3.2,-5.2) R2(-2.4,-5.2) R3(-1.6,-5.2) R7(1.6,-5.2) R8(2.4,-5.2) R9(3.2,-5.2) T1(-3.2,-6) T2(-2.4,-6) T3(-1.6,-6) T7(1.6,-6) T8(2.4,-6) T9(3.2,-6)
CAP-ALUM-D6XL7
  rect 3.353x1.651 smd: 1(-2.55,0) 2(2.55,0)
CN43-01028
  rect 1.829x1.829 hole 1.194: 1(0,0)
  round 1.829 hole 1.194: 2(2.118,2.118) 3(4.345,1.624) 4(5.433,-0.38) 5(4.634,-2.516) 6(2.498,-3.315) 7(0.494,-2.227) 8(2.69,-0.572)
CNOSTTC03
  rect 1.935x1.935 hole 1.3: 1(0,0)
  round 1.935 hole 1.3: 2(5.08,0) 3(10.16,0)
CNRJ45-1X1WLED
  round 3.2 hole 3.2 unplated: (-1.27,-6.35) (10.16,-6.35)
  rect 1.525x1.525 hole 0.89: 1(0,0)
  round 1.525 hole 0.89: 2(1.27,2.54) 3(2.54,0) 4(3.81,2.54) 5(5.08,0) 6(6.35,2.54) 7(7.62,0) 8(8.89,2.54)
  round 1.655 hole 1.02: 9(11.17,-8.89) 10(11.17,-10.92) 11(-2.28,-8.89) 12(-2.28,-10.92)
  round 2.337 hole 1.702: SHLD1(-3.43,-3.3) SHLD2(12.32,-3.3)
CNRJ45-1X1WLED-598M
  round 3.2 hole 3.2 unplated: (0,-8.89) (11.43,-8.89)
  rect 1.525x1.525 hole 0.89: 1(0,0)
  round 1.525 hole 0.89: 2(1.27,-2.54) 3(2.54,0) 4(3.81,-2.54) 5(5.08,0) 6(6.35,-2.54) 7(7.62,0) 8(8.89,-2.54) 9(10.16,0) 10(11.43,-2.54)
  round 1.655 hole 1.02: 11(12.44,-11.43) 12(12.44,-13.46) 13(-1.01,-11.43) 14(-1.01,-13.46)
  round 2.337 hole 1.702: SHLD1(-2.035,-5.84) SHLD2(13.465,-5.84)
CONN_OSTTC02
  round 1.778 hole 1.27: 1(0,0) 2(5.08,0)
DCT8
  rect 1.6x0.3 smd: 1(-1.7,0.975) 2(-1.7,0.325) 3(-1.7,-0.325) 4(-1.7,-0.975) 5(1.7,-0.975) 6(1.7,-0.325) 7(1.7,0.325) 8(1.7,0.975)
DRCPSO_10PIN
  rect 0.305x1.092 smd: 1(-1,-1.625) 2(-0.5,-1.625) 3(0,-1.625) 4(0.5,-1.625) 5(1,-1.625) 6(1,1.625) 7(0.5,1.625) 8(0,1.625) 9(-0.5,1.625) 10(-1,1.625)
  custom 0.41x0.41 smd: 11(0,0)
HDR2X5-330M
  rect 1.795x1.795 hole 1.16: 1(0,0)
  round 1.795 hole 1.16: 2(2.54,0) 3(0,-2.54) 4(2.54,-2.54) 5(0,-5.08) 6(2.54,-5.08) 7(0,-7.62) 8(2.54,-7.62) 9(0,-10.16) 10(2.54,-10.16)
HDR2X20-335M
  rect 1.524x1.524 hole 0.889: 1(0,0)
  round 1.524 hole 0.889: 2(0,2.54) 3(2.54,0) 4(2.54,2.54) 5(5.08,0) 6(5.08,2.54) 7(7.62,0) 8(7.62,2.54) 9(10.16,0) 10(10.16,2.54) 11(12.7,0) 12(12.7,2.54) 13(15.24,0) 14(15.24,2.54) 15(17.78,0) 16(17.78,2.54) 17(20.32,0) 18(20.32,2.54) 19(22.86,0) 20(22.86,2.54) 21(25.4,0) 22(25.4,2.54) 23(27.94,0) 24(27.94,2.54) 25(30.48,0) 26(30.48,2.54) 27(33.02,0) 28(33.02,2.54) 29(35.56,0) 30(35.56,2.54) 31(38.1,0) 32(38.1,2.54) 33(40.64,0) 34(40.64,2.54) 35(43.18,0) 36(43.18,2.54) 37(45.72,0) 38(45.72,2.54) 39(48.26,0) 40(48.26,2.54)
HDR2X30-2MM-177M
  rect 1.524x1.524 hole 0.838: 1(0,0)
  round 1.524 hole 0.838: 2(0,2) 3(2,0) 4(2,2) 5(4,0) 6(4,2) 7(6,0) 8(6,2) 9(8,0) 10(8,2) 11(10,0) 12(10,2) 13(12,0) 14(12,2) 15(14,0) 16(14,2) 17(16,0) 18(16,2) 19(18,0) 20(18,2) 21(20,0) 22(20,2) 23(22,0) 24(22,2) 25(24,0) 26(24,2) 27(26,0) 28(26,2) 29(28,0) 30(28,2) 31(30,0) 32(30,2) 33(32,0) 34(32,2) 35(34,0) 36(34,2) 37(36,0) 38(36,2) 39(38,0) 40(38,2) 41(40,0) 42(40,2) 43(42,0) 44(42,2) 45(44,0) 46(44,2) 47(46,0) 48(46,2) 49(48,0) 50(48,2) 51(50,0) 52(50,2) 53(52,0) 54(52,2) 55(54,0) 56(54,2) 57(56,0) 58(56,2) 59(58,0) 60(58,2)
HDRTSW1X6-330M
  rect 1.651x1.651 hole 1.016: 1(0,0)
  round 1.651 hole 1.016: 2(2.54,0) 3(5.08,0) 4(7.62,0) 5(10.16,0) 6(12.7,0)
HEADER10X2
  rect 0.711x2.87 smd: 1(-5.715,-2.705) 2(-5.715,2.705) 3(-4.445,-2.705) 4(-4.445,2.705) 5(-3.175,-2.705) 6(-3.175,2.705) 7(-1.905,-2.705) 8(-1.905,2.705) 9(-0.635,-2.705) 10(-0.635,2.705) 11(0.635,-2.705) 12(0.635,2.705) 13(1.905,-2.705) 14(1.905,2.705) 15(3.175,-2.705) 16(3.175,2.705) 17(4.445,-2.705) 18(4.445,2.705) 19(5.715,-2.705) 20(5.715,2.705)
HEADER_2X1
  rect 1.778x1.778 hole 1.016: 1(0,0)
  round 1.778 hole 1.016: 2(0,2.54)
HEADER_3X1
  rect 1.651x1.651 hole 1.016: 1(0,0)
  round 1.651 hole 1.016: 2(2.54,0) 3(5.08,0)
HF70ACB201209
  rect 1x1 smd: 1(-1,0) 2(1,0)
HTSSOP-28P-47M
  rect 0.3x1.6 smd: 1(-4.225,-2.8) 2(-3.575,-2.8) 3(-2.925,-2.8) 4(-2.275,-2.8) 5(-1.625,-2.8) 6(-0.975,-2.8) 7(-0.325,-2.8) 8(0.325,-2.8) 9(0.975,-2.8) 10(1.625,-2.8) 11(2.275,-2.8) 12(2.925,-2.8) 13(3.575,-2.8) 14(4.225,-2.8) 15(4.225,2.8) 16(3.575,2.8) 17(2.925,2.8) 18(2.275,2.8) 19(1.625,2.8) 20(0.975,2.8) 21(0.325,2.8) 22(-0.325,2.8) 23(-0.975,2.8) 24(-1.625,2.8) 25(-2.275,2.8) 26(-2.925,2.8) 27(-3.575,2.8) 28(-4.225,2.8)
  rect 9.7x3.4 smd: TPAD(0,0)
IND4X4-83M
  rect 1.473x3.683 smd: 1(-1.219,0) 2(1.219,0)
INDMSS1038
  rect 3.556x1.778 smd: 1(0,4.699) 2(0,-4.699)
INDMSS6122
  rect 6x2 smd: 1(0,2) 2(0,-2)
INDMSS6132
  rect 6x2 smd: 1(0,2) 2(0,-2)
LED-SM1210
  rect 1.5x1 smd: 1(-1.75,0.7) 2(-1.75,-0.7) 3(1.75,0.7) 4(1.75,-0.7)
LQFP64PIN
  rect 1.5x0.3 smd: 1(-5.7,3.75) 2(-5.7,3.25) 3(-5.7,2.75) 4(-5.7,2.25) 5(-5.7,1.75) 6(-5.7,1.25) 7(-5.7,0.75) 8(-5.7,0.25) 9(-5.7,-0.25) 10(-5.7,-0.75) 11(-5.7,-1.25) 12(-5.7,-1.75) 13(-5.7,-2.25) 14(-5.7,-2.75) 15(-5.7,-3.25) 16(-5.7,-3.75) 33(5.7,-3.75) 34(5.7,-3.25) 35(5.7,-2.75) 36(5.7,-2.25) 37(5.7,-1.75) 38(5.7,-1.25) 39(5.7,-0.75) 40(5.7,-0.25) 41(5.7,0.25) 42(5.7,0.75) 43(5.7,1.25) 44(5.7,1.75) 45(5.7,2.25) 46(5.7,2.75) 47(5.7,3.25) 48(5.7,3.75)
  rect 0.3x1.5 smd: 17(-3.75,-5.7) 18(-3.25,-5.7) 19(-2.75,-5.7) 20(-2.25,-5.7) 21(-1.75,-5.7) 22(-1.25,-5.7) 23(-0.75,-5.7) 24(-0.25,-5.7) 25(0.25,-5.7) 26(0.75,-5.7) 27(1.25,-5.7) 28(1.75,-5.7) 29(2.25,-5.7) 30(2.75,-5.7) 31(3.25,-5.7) 32(3.75,-5.7) 49(3.75,5.7) 50(3.25,5.7) 51(2.75,5.7) 52(2.25,5.7) 53(1.75,5.7) 54(1.25,5.7) 55(0.75,5.7) 56(0.25,5.7) 57(-0.25,5.7) 58(-0.75,5.7) 59(-1.25,5.7) 60(-1.75,5.7) 61(-2.25,5.7) 62(-2.75,5.7) 63(-3.25,5.7) 64(-3.75,5.7)
MBRS140T
  rect 2.007x2.489 smd: 1(-2.045,0) 2(2.045,0)
MC-306
  rect 1.3x1.9 smd: 1(-2.75,-1.6) 2(2.75,-1.6) 3(2.75,1.6) 4(-2.75,1.6)
QFN4X4-20-39M
  rect 1x0.28 smd: 1(-1.9,1) 2(-1.9,0.5) 3(-1.9,0) 4(-1.9,-0.5) 5(-1.9,-1) 11(1.9,-1) 12(1.9,-0.5) 13(1.9,0) 14(1.9,0.5) 15(1.9,1)
  rect 0.28x1 smd: 6(-1,-1.9) 7(-0.5,-1.9) 8(0,-1.9) 9(0.5,-1.9) 10(1,-1.9) 16(1,1.9) 17(0.5,1.9) 18(0,1.9) 19(-0.5,1.9) 20(-1,1.9)
  rect 2.25x2.25 smd: TPAD(0,0)
QFN5X5-32-39M
  custom 0.075x0.075 smd: 1(-2.475,1.75) 2(-2.475,1.25) 3(-2.475,0.75) 4(-2.475,0.25) 5(-2.475,-0.25) 6(-2.475,-0.75) 7(-2.475,-1.25) 8(-2.475,-1.75) 9(-1.75,-2.475) 10(-1.25,-2.475) 11(-0.75,-2.475) 12(-0.25,-2.475) 13(0.25,-2.475) 14(0.75,-2.475) 15(1.25,-2.475) 16(1.75,-2.475) 17(2.475,-1.75) 18(2.475,-1.25) 19(2.475,-0.75) 20(2.475,-0.25) 21(2.475,0.25) 22(2.475,0.75) 23(2.475,1.25) 24(2.475,1.75) 25(1.75,2.475) 26(1.25,2.475) 27(0.75,2.475) 28(0.25,2.475) 29(-0.25,2.475) 30(-0.75,2.475) 31(-1.25,2.475) 32(-1.75,2.475)
  rect 3x3 smd: TPAD(0,0)
QFN7X7-48
  rect 0.85x0.28 smd: 1(-3.475,2.75) 2(-3.475,2.25) 3(-3.475,1.75) 4(-3.475,1.25) 5(-3.475,0.75) 6(-3.475,0.25) 7(-3.475,-0.25) 8(-3.475,-0.75) 9(-3.475,-1.25) 10(-3.475,-1.75) 11(-3.475,-2.25) 12(-3.475,-2.75) 25(3.475,-2.75) 26(3.475,-2.25) 27(3.475,-1.75) 28(3.475,-1.25) 29(3.475,-0.75) 30(3.475,-0.25) 31(3.475,0.25) 32(3.475,0.75) 33(3.475,1.25) 34(3.475,1.75) 35(3.475,2.25) 36(3.475,2.75)
  rect 0.28x0.85 smd: 13(-2.75,-3.475) 14(-2.25,-3.475) 15(-1.75,-3.475) 16(-1.25,-3.475) 17(-0.75,-3.475) 18(-0.25,-3.475) 19(0.25,-3.475) 20(0.75,-3.475) 21(1.25,-3.475) 22(1.75,-3.475) 23(2.25,-3.475) 24(2.75,-3.475) 37(2.75,3.475) 38(2.25,3.475) 39(1.75,3.475) 40(1.25,3.475) 41(0.75,3.475) 42(0.25,3.475) 43(-0.25,3.475) 44(-0.75,3.475) 45(-1.25,3.475) 46(-1.75,3.475) 47(-2.25,3.475) 48(-2.75,3.475)
  rect 5.15x5.15 smd: 49(0,0)
RAPC712
  round 4.064 hole 3.556: 1(0,0)
  round 3.683 hole 3.048: 2(-2.997,-4.801) 3(-6.248,0)
SC70-5-43M
  rect 0.95x0.4 smd: 1(-1.075,0.65) 2(-1.075,0) 3(-1.075,-0.65) 4(1.075,-0.65) 5(1.075,0.65)
SCKAXK7L24
  custom 0.25x0.25 smd: (-3.1,2.3) (-3.1,-2.3) (3.1,2.3) (3.1,-2.3)
  rect 0.22x0.8 smd: 1(-2.2,-2.4) 2(-1.8,-2.4) 3(-1.4,-2.4) 4(-1,-2.4) 5(-0.6,-2.4) 6(-0.2,-2.4) 7(0.2,-2.4) 8(0.6,-2.4) 9(1,-2.4) 10(1.4,-2.4) 11(1.8,-2.4) 12(2.2,-2.4) 13(2.2,2.4) 14(1.8,2.4) 15(1.4,2.4) 16(1,2.4) 17(0.6,2.4) 18(0.2,2.4) 19(-0.2,2.4) 20(-0.6,2.4) 21(-1,2.4) 22(-1.4,2.4) 23(-1.8,2.4) 24(-2.2,2.4)
SCKBGA625
  round 1.7 hole 1.7 unplated: (-9.863,9.863) (-9.863,-9.863) (9.863,9.863) (9.863,-9.863)
  round 0.85 hole 0.85 unplated: (-9.863,-4.783) (9.863,7.323)
SD-MICRO-SCHA5B0300
  rect 0.914x0.457 smd: 1(-7.257,0) 2(-7.257,-0.7) 3(-7.257,-1.4) 4(-7.257,-2.1) 5(7.257,-2.1) 6(7.257,-1.4) 7(7.257,-0.7) 8(7.257,0)
  rect 0.508x0.889 smd: 9(3.775,9.989) 10(-5.975,9.989)
  rect 0.889x2.007 smd: 11(-7.25,7.635) 12(7.25,6.335)
  rect 1.118x1.524 smd: 13(-7.196,-3.365) 14(7.196,-3.365)
  rect 1.194x1.092 smd: 15(-3.425,10.488) 16(2.575,10.488)
SM-7351-CAP-0402
  round 0.635 smd: 1(-0.508,0) 2(0.508,0)
SM-7351-CAP-0603
  rect 1.092x1.041 smd: 1(-0.85,0) 2(0.85,0)
SM-7351-CAP-0805
  rect 1.346x1.524 smd: 1(-1,0) 2(1,0)
SM-7351-CAP-1206
  rect 1.2x1.85 smd: 1(1.6,0) 2(-1.6,0)
SM-7351-IND-0603
  rect 1.143x1.092 smd: 1(-0.9,0) 2(0.9,0)
SM-7351-IND-0805
  rect 1.397x1.549 smd: 1(-0.95,0) 2(0.95,0)
SM-7351-RES-0402
  round 0.635 smd: 1(-0.508,0) 2(0.508,0)
SM-7351-RES-0603
  rect 1.143x1.092 smd: 1(-0.9,0) 2(0.9,0)
SM-7351-RES-1206
  rect 1.57x1.78 smd: 1(-1.165,0) 2(1.165,0)
SM-7351-RES-1210
  rect 1.15x2.7 smd: 1(-1.5,0) 2(1.5,0)
SM-SO-SC70-5
  rect 0.406x1.016 smd: 1(-0.65,-0.95) 2(0,-0.95) 3(0.65,-0.95) 4(0.65,0.95) 5(-0.65,0.95)
SM_LED_0805
  rect 1.15x1.194 smd: 1(1.125,0) 2(-1.125,0)
SM_OSC_ABM3
  rect 1.9x2.4 smd: 1(-2.05,0) 2(2.05,0)
SMCJ26CA
  rect 2.6x3.2 smd: 1(-3.6,0) 2(3.6,0)
SMD7343-122M
  rect 2.35x2.45 smd: 1(-3.1,0) 2(3.1,0)
SMD_MELF0102
  rect 1x1.2 smd: 1(-1,0) 2(1,0)
SMD_SLF7055T
  rect 1.5x2.2 smd: 1(-3.15,0) 2(3.15,0)
SMDFUSEBLK
  rect 4.242x3.81 smd: 1(-3.175,0) 2(3.175,0)
SMDSC70-6
  rect 0.406x1.016 smd: 1(-0.65,-0.95) 2(0,-0.95) 3(0.65,-0.95) 4(0.65,0.95) 5(0,0.95) 6(-0.65,0.95)
SOD-123
  rect 0.914x1.219 smd: 1(1.651,0) 2(-1.651,0)
SOIC-8
  rect 0.6x2 smd: 1(-1.905,-2.4) 2(-0.635,-2.4) 3(0.635,-2.4) 4(1.905,-2.4) 5(1.905,2.4) 6(0.635,2.4) 7(-0.635,2.4) 8(-1.905,2.4)
SOIC_8
  rect 0.61x2.184 smd: 1(-1.905,-2.603)
  oval 0.61x2.184 smd: 2(-0.635,-2.603) 3(0.635,-2.603) 4(1.905,-2.603) 5(1.905,2.603) 6(0.635,2.603) 7(-0.635,2.603) 8(-1.905,2.603)
SOIC_16PIN_DW
  rect 0.6x2 smd: 1(-4.445,-4.7) 2(-3.175,-4.7) 3(-1.905,-4.7) 4(-0.635,-4.7) 5(0.635,-4.7) 6(1.905,-4.7) 7(3.175,-4.7) 8(4.445,-4.7) 9(4.445,4.7) 10(3.175,4.7) 11(1.905,4.7) 12(0.635,4.7) 13(-0.635,4.7) 14(-1.905,4.7) 15(-3.175,4.7) 16(-4.445,4.7)
SON2X1-8-16M
  rect 0.85x0.2 smd: 1(-0.55,0.6) 2(-0.55,0.2) 3(-0.55,-0.2) 4(-0.55,-0.6) 5(0.55,-0.6) 6(0.55,-0.2) 7(0.55,0.2) 8(0.55,0.6)
SOT23-3
  rect 0.787x0.889 smd: D(0,1.003) G(-0.94,-1.003) S(0.94,-1.003)
SOT23-3-44M
  rect 0.6x1.05 smd: 1(-0.95,-1.185) 2(0.95,-1.185) 3(0,1.185)
SOT23-5
  rect 1.016x0.635 smd: 1(1.194,-0.94) 2(1.194,0) 3(1.194,0.94) 4(-1.194,0.94) 5(-1.194,-0.94)
SOT223-4
  rect 2.2x1.2 smd: D1(-2.95,0) G(-2.95,2.3) S(-2.95,-2.3)
  rect 2.2x3.2 smd: D2(2.95,0)
SW_B3SL-1022P
  rect 2.75x1 smd: 1(2.875,-2) 2(-2.875,-2) 3(2.875,2) 4(-2.875,2)
TH_TP_5002
  round 1.778 hole 1.016: 1(0,0)
TP_SMD1MMCIRCLE
  round 1.016 smd: 1(0,0)
TSSOP4X6-20
  rect 0.4x1.6 smd: 1(-2.925,-2.9) 2(-2.275,-2.9) 3(-1.625,-2.9) 4(-0.975,-2.9) 5(-0.325,-2.9) 6(0.325,-2.9) 7(0.975,-2.9) 8(1.625,-2.9) 9(2.275,-2.9) 10(2.925,-2.9) 11(2.925,2.9) 12(2.275,2.9) 13(1.625,2.9) 14(0.975,2.9) 15(0.325,2.9) 16(-0.325,2.9) 17(-0.975,2.9) 18(-1.625,2.9) 19(-2.275,2.9) 20(-2.925,2.9)
TSSOP5X4-14-47M
  rect 1.4x0.4 smd: 1(-2.95,1.95) 2(-2.95,1.3) 3(-2.95,0.65) 4(-2.95,0) 5(-2.95,-0.65) 6(-2.95,-1.3) 7(-2.95,-1.95) 8(2.95,-1.95) 9(2.95,-1.3) 10(2.95,-0.65) 11(2.95,0) 12(2.95,0.65) 13(2.95,1.3) 14(2.95,1.95)
TSSOP8X4-24-47M
  rect 1.4x0.4 smd: 1(-2.95,3.575) 2(-2.95,2.925) 3(-2.95,2.275) 4(-2.95,1.625) 5(-2.95,0.975) 6(-2.95,0.325) 7(-2.95,-0.325) 8(-2.95,-0.975) 9(-2.95,-1.625) 10(-2.95,-2.275) 11(-2.95,-2.925) 12(-2.95,-3.575) 13(2.95,-3.575) 14(2.95,-2.925) 15(2.95,-2.275) 16(2.95,-1.625) 17(2.95,-0.975) 18(2.95,-0.325) 19(2.95,0.325) 20(2.95,0.975) 21(2.95,1.625) 22(2.95,2.275) 23(2.95,2.925) 24(2.95,3.575)
U_5_DCK
  rect 0.432x1.27 smd: 1(0.65,0.775) 2(0,0.775) 3(-0.65,0.775) 4(-0.65,-0.884) 5(0.65,-0.884)
U_5_DRL
  rect 0.3x0.45 smd: 1(-0.5,-0.675) 2(0,-0.675) 3(0.5,-0.675) 4(0.5,0.675) 5(-0.5,0.675)
U_6_DBV
  rect 0.686x0.991 smd: 1(-0.953,-1.295) 2(0,-1.295) 3(0.953,-1.295) 4(0.953,1.295) 5(0,1.295) 6(-0.953,1.295)
U_10_RSE
  rect 0.3x0.58 smd: 1(-0.75,-0.635) 2(-0.25,-0.635) 3(0.25,-0.635) 4(0.75,-0.635) 6(0.75,0.635) 7(0.25,0.635) 8(-0.25,0.635) 9(-0.75,0.635)
  rect 0.63x0.35 smd: 5(0.86,0) 10(-0.86,0)
U_16_D
  rect 0.6x2 smd: 1(-4.445,-2.4) 2(-3.175,-2.4) 3(-1.905,-2.4) 4(-0.635,-2.4) 5(0.635,-2.4) 6(1.905,-2.4) 7(3.175,-2.4) 8(4.445,-2.4) 9(4.445,2.4) 10(3.175,2.4) 11(1.905,2.4) 12(0.635,2.4) 13(-0.635,2.4) 14(-1.905,2.4) 15(-3.175,2.4) 16(-4.445,2.4)
U_16_PW
  rect 0.35x1.6 smd: 1(-2.275,-2.8) 2(-1.625,-2.8) 3(-0.975,-2.8) 4(-0.325,-2.8) 5(0.325,-2.8) 6(0.975,-2.8) 7(1.625,-2.8) 8(2.275,-2.8) 9(2.275,2.8) 10(1.625,2.8) 11(0.975,2.8) 12(0.325,2.8) 13(-0.325,2.8) 14(-0.975,2.8) 15(-1.625,2.8) 16(-2.275,2.8)
U_28_PWP
  rect 0.3x1.45 smd: 1(-4.225,-2.8) 2(-3.575,-2.8) 3(-2.925,-2.8) 4(-2.275,-2.8) 5(-1.625,-2.8) 6(-0.975,-2.8) 7(-0.325,-2.8) 8(0.325,-2.8) 9(0.975,-2.8) 10(1.625,-2.8) 11(2.275,-2.8) 12(2.925,-2.8) 13(3.575,-2.8) 14(4.225,-2.8) 15(4.225,2.8) 16(3.575,2.8) 17(2.925,2.8) 18(2.275,2.8) 19(1.625,2.8) 20(0.975,2.8) 21(0.325,2.8) 22(-0.325,2.8) 23(-0.975,2.8) 24(-1.625,2.8) 25(-2.275,2.8) 26(-2.925,2.8) 27(-3.575,2.8) 28(-4.225,2.8)
  rect 9.7x3.4 smd: TH_PD(0,0)
unnamed
  round 1.016 smd: 1(0,0)
unnamed#2
  round 3.505 hole 3.505 unplated: (0,0)
WCSP1X1-6-20M
  round 0.184 smd: A1(-0.25,0.5) A2(0.25,0.5) B1(-0.25,0) B2(0.25,0) C1(-0.25,-0.5) C2(0.25,-0.5)
XTAL2X3-30M
  rect 1.15x1.4 smd: 1(-0.8,1.2) 2(-0.8,-1.2) 3(0.8,-1.2) 4(0.8,1.2)
ZX62-AB-5PA
  rect 1.9x1.9 smd: (-1.2,-2.675) (1.2,-2.675)
  rect 0.4x1.35 smd: 1(-1.3,0) 2(-0.65,0) 3(0,0) 4(0.65,0) 5(1.3,0)
  rect 2.1x1.6 smd: S1(-3.1,-0.125) S2(3.1,-0.125)
  rect 1.8x1.9 smd: S3(-4.1,-2.675) S4(4.1,-2.675)

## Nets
AGND: C2.2 C15.2 J5.1 R17.2(P2)
AGNDFRAME_PRUETH0: C137.2 J6.SHLD1 J6.SHLD2
AGNDFRAME_PRUETH1: C188.2 J9.SHLD1 J9.SHLD2
